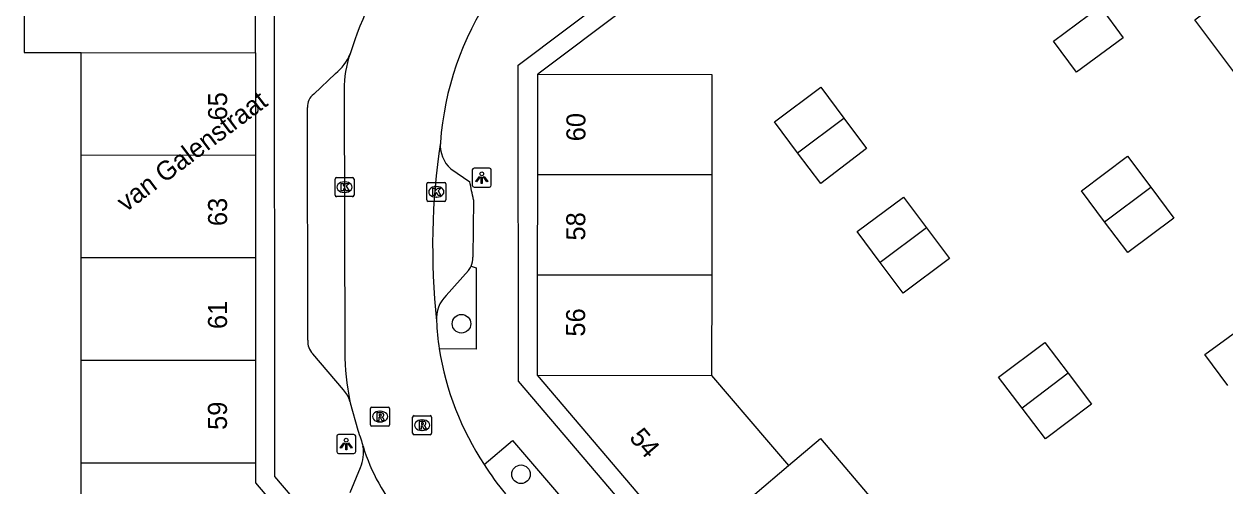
# Model space of a CAD drawing. Extents: x 160379 to 161131, y 383940 to 384849.
# Drawn here: x 160473.8 to 160537, y 384676 to 384700.3 of the extents above; entities that cross this region are included whole.
import ezdxf

# ---------------------------------------------------------------- set-up
doc = ezdxf.new("R2010")
doc.units = 0
for name, color, linetype in [('IMGEO_Boom', 7, 'Continuous'), ('IMGEO_Erf', 7, 'Continuous'), ('IMGEO_Kolk', 7, 'Continuous'), ('IMGEO_Lichtpunt', 7, 'Continuous'), ('IMGEO_Openbare_ruimte_label', 7, 'Continuous'), ('IMGEO_Pand', 7, 'Continuous'), ('IMGEO_Pand_nummerreeks', 7, 'Continuous'), ('IMGEO_Parkeervlak_open', 7, 'Continuous'), ('IMGEO_Rijbaan_lokaal_open', 7, 'Continuous'), ('IMGEO_Rioolput', 7, 'Continuous'), ('IMGEO_Voetpad_open', 7, 'Continuous')]:
    doc.layers.add(name, color=color, linetype=linetype)

msp = doc.modelspace()

# ---------------------------------------------------------------- linework, layer by layer
at = {"layer": 'IMGEO_Boom'}
for centre in [(160496.838, 384684.503), (160499.972, 384676.583)]:
    msp.add_circle(centre, 0.489, dxfattribs=at)
at = {"layer": 'IMGEO_Erf'}
msp.add_lwpolyline([(160518.956, 384711.247), (160514.905, 384708.218), (160510.089, 384704.569), (160500.864, 384697.632)], dxfattribs=at)
at = {"layer": 'IMGEO_Kolk'}
for p, q in [((160490.185, 384691.262), (160490.185, 384692.114)), ((160490.26, 384692.188), (160491.112, 384692.188)), ((160490.673, 384691.968), (160490.698, 384691.968)), ((160491.186, 384692.114), (160491.186, 384691.262)), ((160495.014, 384691.015), (160495.014, 384691.867)), ((160495.089, 384691.941), (160495.941, 384691.941)), ((160495.502, 384691.721), (160495.527, 384691.721)), ((160496.015, 384691.867), (160496.015, 384691.015)), ((160491.112, 384691.188), (160490.26, 384691.188)), ((160490.696, 384691.408), (160490.671, 384691.408)), ((160495.525, 384691.161), (160495.5, 384691.161)), ((160495.941, 384690.941), (160495.089, 384690.941))]:
    msp.add_line(p, q, dxfattribs=at)
for points in [[(160490.185, 384691.262), (160490.185, 384692.114)], [(160490.26, 384692.188), (160491.112, 384692.188)], [(160490.506, 384691.888), (160490.629, 384691.888), (160490.629, 384691.737), (160490.759, 384691.888), (160490.923, 384691.888), (160490.777, 384691.737), (160490.93, 384691.488), (160490.778, 384691.488), (160490.693, 384691.652), (160490.629, 384691.585), (160490.629, 384691.488), (160490.506, 384691.488), (160490.506, 384691.888)], [(160491.186, 384692.114), (160491.186, 384691.262)], [(160495.014, 384691.015), (160495.014, 384691.867)], [(160495.089, 384691.941), (160495.941, 384691.941)], [(160495.335, 384691.641), (160495.458, 384691.641), (160495.458, 384691.49), (160495.588, 384691.641), (160495.752, 384691.641), (160495.606, 384691.49), (160495.759, 384691.241), (160495.607, 384691.241), (160495.522, 384691.405), (160495.458, 384691.338), (160495.458, 384691.241), (160495.335, 384691.241), (160495.335, 384691.641)], [(160496.015, 384691.867), (160496.015, 384691.015)], [(160491.112, 384691.188), (160490.26, 384691.188)], [(160495.941, 384690.941), (160495.089, 384690.941)]]:
    msp.add_lwpolyline(points, dxfattribs=at)
for centre, start, end in [((160490.262, 384692.112), 91.55205, 178.44795), ((160490.262, 384692.112), 91.55205, 178.44795), ((160491.11, 384692.112), 1.55205, 88.44795), ((160491.11, 384692.112), 1.55205, 88.44795), ((160495.091, 384691.865), 91.55205, 178.44795), ((160495.091, 384691.865), 91.55205, 178.44795), ((160495.939, 384691.865), 1.55205, 88.44795), ((160495.939, 384691.865), 1.55205, 88.44795), ((160490.262, 384691.264), 181.55205, 268.44795), ((160490.262, 384691.264), 181.55205, 268.44795), ((160491.11, 384691.264), 271.55205, 358.44795), ((160491.11, 384691.264), 271.55205, 358.44795), ((160495.091, 384691.017), 181.55205, 268.44795), ((160495.091, 384691.017), 181.55205, 268.44795), ((160495.939, 384691.017), 271.55205, 358.44795), ((160495.939, 384691.017), 271.55205, 358.44795)]:
    msp.add_arc(centre, 0.0765, start, end, dxfattribs=at)
for centre, major_axis, ratio, start_param, end_param in [((160490.672, 384691.688), (-0.387, 0.002), 0.722429, 4.712389, 7.853982), ((160490.697, 384691.688), (-0.39, 0.002), 0.717154, 1.570796, 4.712389), ((160495.501, 384691.441), (-0.387, 0.002), 0.722429, 4.712389, 7.853982), ((160495.526, 384691.441), (-0.39, 0.002), 0.717154, 1.570796, 4.712389)]:
    msp.add_ellipse(centre, major_axis=major_axis, ratio=ratio, start_param=start_param, end_param=end_param, dxfattribs=at)
at = {"layer": 'IMGEO_Lichtpunt'}
for p, q in [((160497.407, 384692.593), (160497.407, 384691.786)), ((160497.407, 384692.593), (160497.407, 384691.786)), ((160498.309, 384692.688), (160497.501, 384692.688)), ((160498.309, 384692.688), (160497.501, 384692.688)), ((160498.403, 384691.786), (160498.403, 384692.593)), ((160498.403, 384691.786), (160498.403, 384692.593)), ((160497.501, 384691.692), (160498.309, 384691.692)), ((160497.501, 384691.692), (160498.309, 384691.692)), ((160490.276, 384678.58), (160490.276, 384677.773)), ((160490.276, 384678.58), (160490.276, 384677.773)), ((160491.178, 384678.675), (160490.37, 384678.675)), ((160491.178, 384678.675), (160490.37, 384678.675)), ((160491.272, 384677.773), (160491.272, 384678.58)), ((160491.272, 384677.773), (160491.272, 384678.58)), ((160490.37, 384677.679), (160491.178, 384677.679)), ((160490.37, 384677.679), (160491.178, 384677.679))]:
    msp.add_line(p, q, dxfattribs=at)
for points in [[(160497.781, 384692.257), (160497.82, 384692.229), (160497.632, 384691.967), (160497.594, 384691.994), (160497.781, 384692.257)], [(160497.993, 384692.229), (160498.031, 384692.256), (160498.218, 384691.994), (160498.179, 384691.966), (160497.993, 384692.229)], [(160497.883, 384692.209), (160497.93, 384692.209), (160497.93, 384691.887), (160497.883, 384691.887), (160497.883, 384692.209)], [(160490.65, 384678.244), (160490.689, 384678.216), (160490.501, 384677.954), (160490.463, 384677.981), (160490.65, 384678.244)], [(160490.752, 384678.196), (160490.799, 384678.196), (160490.799, 384677.874), (160490.752, 384677.874), (160490.752, 384678.196)], [(160490.862, 384678.216), (160490.9, 384678.243), (160491.087, 384677.981), (160491.048, 384677.953), (160490.862, 384678.216)]]:
    msp.add_lwpolyline(points, dxfattribs=at)
for centre in [(160497.906, 384692.391), (160490.775, 384678.378)]:
    msp.add_circle(centre, 0.0994, dxfattribs=at)
for centre, start, end in [((160497.501, 384692.593), 90, 180), ((160497.501, 384692.593), 90, 180), ((160498.309, 384692.593), 0, 90), ((160498.309, 384692.593), 0, 90), ((160497.501, 384691.786), 180, 270), ((160497.501, 384691.786), 180, 270), ((160498.309, 384691.786), 270, 0), ((160498.309, 384691.786), 270, 360), ((160490.37, 384678.58), 90, 180), ((160490.37, 384678.58), 90, 180), ((160491.178, 384678.58), 0, 90), ((160491.178, 384678.58), 0, 90), ((160490.37, 384677.773), 180, 270), ((160490.37, 384677.773), 180, 270), ((160491.178, 384677.773), 270, 0), ((160491.178, 384677.773), 270, 360)]:
    msp.add_arc(centre, 0.0946, start, end, dxfattribs=at)
at = {"layer": 'IMGEO_Pand'}
for points in [[(160538.684, 384696.143), (160535.415, 384700.495), (160537.673, 384702.203), (160542.734, 384706.008)], [(160476.827, 384704.172), (160473.83, 384704.176), (160473.823, 384698.766), (160476.827, 384698.765)], [(160486.009, 384698.761), (160486.012, 384704.16)], [(160527.994, 384699.366), (160530.449, 384701.194), (160531.654, 384699.542), (160529.203, 384697.743), (160527.994, 384699.366)], [(160476.826, 384693.366), (160476.827, 384698.765)], [(160476.827, 384698.765), (160486.009, 384698.761)], [(160486.009, 384698.761), (160486.006, 384693.362)], [(160500.855, 384692.343), (160500.864, 384697.632)], [(160500.864, 384697.632), (160510.014, 384697.611), (160510.009, 384692.334)], [(160514.524, 384693.501), (160513.308, 384695.122), (160515.75, 384696.942), (160516.957, 384695.325)], [(160516.957, 384695.325), (160518.155, 384693.72), (160515.74, 384691.879), (160514.524, 384693.501)], [(160514.524, 384693.501), (160516.957, 384695.325)], [(160476.826, 384687.967), (160476.826, 384693.366)], [(160486.006, 384693.362), (160476.826, 384693.366)], [(160486.006, 384693.362), (160486.004, 384687.962)], [(160530.677, 384689.872), (160529.463, 384691.499), (160531.883, 384693.322), (160533.103, 384691.681)], [(160500.846, 384687.066), (160500.855, 384692.343)], [(160510.009, 384692.334), (160500.855, 384692.343)], [(160510.009, 384692.334), (160510.004, 384687.058)], [(160533.103, 384691.681), (160534.313, 384690.052), (160531.89, 384688.244), (160530.677, 384689.872)], [(160530.677, 384689.872), (160533.103, 384691.681)], [(160518.865, 384687.733), (160517.649, 384689.361), (160520.097, 384691.163), (160521.3, 384689.551)], [(160521.3, 384689.551), (160522.508, 384687.933), (160520.08, 384686.105), (160518.865, 384687.733)], [(160521.3, 384689.551), (160518.865, 384687.733)], [(160476.826, 384682.568), (160476.826, 384687.967)], [(160486.004, 384687.962), (160476.826, 384687.967)], [(160486.004, 384687.962), (160486.001, 384682.563)], [(160500.837, 384681.797), (160500.846, 384687.066)], [(160510.004, 384687.058), (160500.846, 384687.066)], [(160510.004, 384687.058), (160509.999, 384681.781)], [(160537.151, 384681.253), (160535.945, 384682.882), (160538.404, 384684.671), (160539.598, 384683.063)], [(160526.333, 384680.065), (160525.101, 384681.69), (160527.524, 384683.518), (160528.754, 384681.9)], [(160476.825, 384677.176), (160476.826, 384682.568)], [(160486.001, 384682.563), (160476.826, 384682.568)], [(160486.001, 384682.563), (160485.998, 384677.164)], [(160508.724, 384672.527), (160500.837, 384681.797)], [(160500.837, 384681.797), (160509.999, 384681.781)], [(160509.999, 384681.781), (160513.001, 384678.269), (160514.045, 384677.042)], [(160528.754, 384681.9), (160529.992, 384680.272), (160527.565, 384678.439), (160526.333, 384680.065)], [(160528.754, 384681.9), (160526.333, 384680.065)], [(160514.045, 384677.042), (160515.722, 384678.465), (160519.266, 384674.291)], [(160480.106, 384668.915), (160476.825, 384672.757), (160476.825, 384677.176)], [(160485.998, 384677.164), (160476.825, 384677.176)], [(160485.998, 384677.164), (160485.998, 384676.129), (160487.085, 384674.855)], [(160508.724, 384672.527), (160514.045, 384677.042)]]:
    msp.add_lwpolyline(points, dxfattribs=at)
at = {"layer": 'IMGEO_Parkeervlak_open'}
msp.add_lwpolyline([(160496.035, 384685.989), (160497.205, 384687.3)], dxfattribs=at)
for centre, radius, start, end in [((160496.366, 384687.982), 1.081, 320.85877, 335.0851), ((160497.2, 384684.784), 1.676, 134.05146, 184.7055)]:
    msp.add_arc(centre, radius, start, end, dxfattribs=at)
at = {"layer": 'IMGEO_Rijbaan_lokaal_open'}
for points in [[(160490.673, 384696.812), (160490.703, 384683.015)], [(160490.968, 384680.419), (160490.976, 384680.376), (160490.983, 384680.347), (160491.378, 384678.909)]]:
    msp.add_lwpolyline(points, dxfattribs=at)
for centre, radius, start, end in [((160513.856, 384691.277), 24.056, 147.27903, 162.02332), ((160511.705, 384692.883), 16.016, 146.12876, 175.84549), ((160496.016, 384696.929), 5.344, 160.63674, 181.25606), ((160532.28, 384688.561), 36.958, 171.46975, 186.07927), ((160509.083, 384685.192), 13.563, 182.30455, 188.52816), ((160503.266, 384682.986), 12.563, 179.86745, 191.7897), ((160510.846, 384685.589), 15.367, 189.0148, 213.52805), ((160502.089, 384682.502), 11.298, 198.54396, 201.04505), ((160505.081, 384682.198), 14.047, 195.49689, 197.13748), ((160502.035, 384681.316), 10.876, 197.42748, 219.69327), ((160508.488, 384683.498), 12.254, 211.47009, 220.39467)]:
    msp.add_arc(centre, radius, start, end, dxfattribs=at)
at = {"layer": 'IMGEO_Rioolput'}
for p, q in [((160492.055, 384679.191), (160492.055, 384680.043)), ((160492.13, 384680.117), (160492.982, 384680.117)), ((160492.543, 384679.897), (160492.568, 384679.897)), ((160493.056, 384680.043), (160493.056, 384679.191)), ((160494.343, 384679.666), (160495.195, 384679.666)), ((160492.982, 384679.117), (160492.13, 384679.117)), ((160492.566, 384679.337), (160492.541, 384679.337)), ((160494.268, 384678.74), (160494.268, 384679.592)), ((160494.756, 384679.446), (160494.781, 384679.446)), ((160495.269, 384679.592), (160495.269, 384678.74)), ((160495.195, 384678.666), (160494.343, 384678.666)), ((160494.779, 384678.886), (160494.754, 384678.886))]:
    msp.add_line(p, q, dxfattribs=at)
for points in [[(160492.055, 384679.191), (160492.055, 384680.043)], [(160492.13, 384680.117), (160492.982, 384680.117)], [(160492.644, 384679.815), (160492.392, 384679.817), (160492.392, 384679.417)], [(160492.57, 384679.736), (160492.516, 384679.736), (160492.516, 384679.655)], [(160492.516, 384679.655), (160492.568, 384679.655)], [(160493.056, 384680.043), (160493.056, 384679.191)], [(160494.343, 384679.666), (160495.195, 384679.666)], [(160492.982, 384679.117), (160492.13, 384679.117)], [(160492.392, 384679.417), (160492.516, 384679.417), (160492.516, 384679.579), (160492.527, 384679.579)], [(160492.574, 384679.55), (160492.645, 384679.417), (160492.785, 384679.417), (160492.72, 384679.543)], [(160494.268, 384678.74), (160494.268, 384679.592)], [(160494.857, 384679.364), (160494.605, 384679.366), (160494.605, 384678.966)], [(160494.605, 384678.966), (160494.729, 384678.966), (160494.729, 384679.128), (160494.74, 384679.128)], [(160494.783, 384679.285), (160494.729, 384679.285), (160494.729, 384679.204)], [(160494.729, 384679.204), (160494.781, 384679.204)], [(160494.787, 384679.099), (160494.858, 384678.966), (160494.998, 384678.966), (160494.933, 384679.092)], [(160495.269, 384679.592), (160495.269, 384678.74)], [(160495.195, 384678.666), (160494.343, 384678.666)]]:
    msp.add_lwpolyline(points, dxfattribs=at)
for centre, radius, start, end in [((160492.132, 384680.041), 0.0765, 91.55205, 178.44795), ((160492.132, 384680.041), 0.0765, 91.55205, 178.44795), ((160492.552, 384679.844), 0.19, 274.7715, 282.96867), ((160492.576, 384679.64), 0.0964, 77.00612, 93.18647), ((160492.59, 384679.697), 0.0378, 276.66336, 79.67722), ((160492.643, 384679.705), 0.109, 350.36119, 89.41601), ((160492.641, 384679.705), 0.112, 277.58423, 350.98172), ((160492.98, 384680.041), 0.0765, 1.55205, 88.44795), ((160492.98, 384680.041), 0.0765, 1.55205, 88.44795), ((160494.345, 384679.59), 0.0765, 91.55205, 178.44795), ((160494.345, 384679.59), 0.0765, 91.55205, 178.44795), ((160495.193, 384679.59), 0.0765, 1.55205, 88.44795), ((160495.193, 384679.59), 0.0765, 1.55205, 88.44795), ((160492.132, 384679.193), 0.0765, 181.55205, 268.44795), ((160492.132, 384679.193), 0.0765, 181.55205, 268.44795), ((160492.526, 384679.526), 0.0533, 26.02933, 88.69889), ((160492.625, 384679.49), 0.108, 29.51342, 73.79051), ((160492.98, 384679.193), 0.0765, 271.55205, 358.44795), ((160492.98, 384679.193), 0.0765, 271.55205, 358.44795), ((160494.739, 384679.075), 0.0533, 26.02933, 88.69889), ((160494.765, 384679.393), 0.19, 274.7715, 282.96867), ((160494.789, 384679.189), 0.0964, 77.00612, 93.18647), ((160494.803, 384679.246), 0.0378, 276.66336, 79.67722), ((160494.856, 384679.254), 0.109, 350.36119, 89.41601), ((160494.854, 384679.254), 0.112, 277.58423, 350.98172), ((160494.838, 384679.039), 0.108, 29.51342, 73.79051), ((160494.345, 384678.742), 0.0765, 181.55205, 268.44795), ((160494.345, 384678.742), 0.0765, 181.55205, 268.44795), ((160495.193, 384678.742), 0.0765, 271.55205, 358.44795), ((160495.193, 384678.742), 0.0765, 271.55205, 358.44795)]:
    msp.add_arc(centre, radius, start, end, dxfattribs=at)
for centre, major_axis, ratio, start_param, end_param in [((160492.542, 384679.617), (-0.387, 0.002), 0.722429, 4.712389, 7.853982), ((160492.567, 384679.617), (-0.39, 0.002), 0.717154, 1.570796, 4.712389), ((160494.755, 384679.166), (-0.387, 0.002), 0.722429, 4.712389, 7.853982), ((160494.78, 384679.166), (-0.39, 0.002), 0.717154, 1.570796, 4.712389)]:
    msp.add_ellipse(centre, major_axis=major_axis, ratio=ratio, start_param=start_param, end_param=end_param, dxfattribs=at)
at = {"layer": 'IMGEO_Voetpad_open'}
for points in [[(160524.356, 384632.684), (160487.022, 384676.465), (160487, 384704.676), (160523.198, 384731.929), (160524.022, 384732.549)], [(160558.691, 384612.377), (160544.574, 384628.905), (160499.831, 384681.477), (160499.817, 384698.107), (160517.199, 384711.18), (160531.839, 384722.221)], [(160489.064, 384696.581), (160490.208, 384697.67)], [(160488.753, 384683.63), (160488.745, 384695.88)], [(160496.283, 384692.645), (160497.274, 384691.975)], [(160497.468, 384691.028), (160497.441, 384688.013)], [(160497.347, 384687.527), (160497.613, 384687.436), (160497.609, 384683.172), (160495.669, 384683.181)], [(160490.634, 384681.023), (160489.014, 384682.922)], [(160498.036, 384677.101), (160499.528, 384678.355), (160502.475, 384674.925), (160502.376, 384674.588)], [(160490.989, 384675.619), (160491.52, 384676.938)]]:
    msp.add_lwpolyline(points, dxfattribs=at)
for centre, radius, start, end in [((160488.759, 384699.547), 2.371, 307.67623, 339.10143), ((160489.522, 384695.95), 0.78, 125.93343, 185.12941), ((160497.396, 384693.893), 1.672, 174.84008, 228.25307), ((160468.478, 384685.583), 29.497, 10.6384, 12.51617), ((160496.393, 384687.964), 1.049, 335.40819, 2.69835), ((160489.673, 384683.567), 0.922, 176.07598, 224.39624), ((160489.534, 384680.02), 1.489, 15.53937, 42.34407), ((160489.793, 384677.72), 1.895, 335.64598, 10.31792)]:
    msp.add_arc(centre, radius, start, end, dxfattribs=at)

# ---------------------------------------------------------------- texts
at = {"layer": 'IMGEO_Openbare_ruimte_label'}
msp.add_text('van Galenstraat', height=1, rotation=36.9959, dxfattribs=at).set_placement((160479.181, 384690.348))
at = {"layer": 'IMGEO_Pand_nummerreeks'}
for s, rotation, p in [('65', 89.97156, (160484.508, 384695.197)), ('60', 89.90281, (160503.358, 384694.1)), ('63', 89.97156, (160484.505, 384689.64)), ('58', 89.90281, (160503.35, 384688.879)), ('61', 89.97156, (160484.502, 384684.222)), ('56', 89.90281, (160503.341, 384683.826)), ('59', 89.97156, (160484.5, 384678.917)), ('54', 310.39331, (160505.624, 384678.486))]:
    msp.add_text(s, height=1, rotation=rotation, dxfattribs=at).set_placement(p)

doc.saveas('drawing.dxf')
